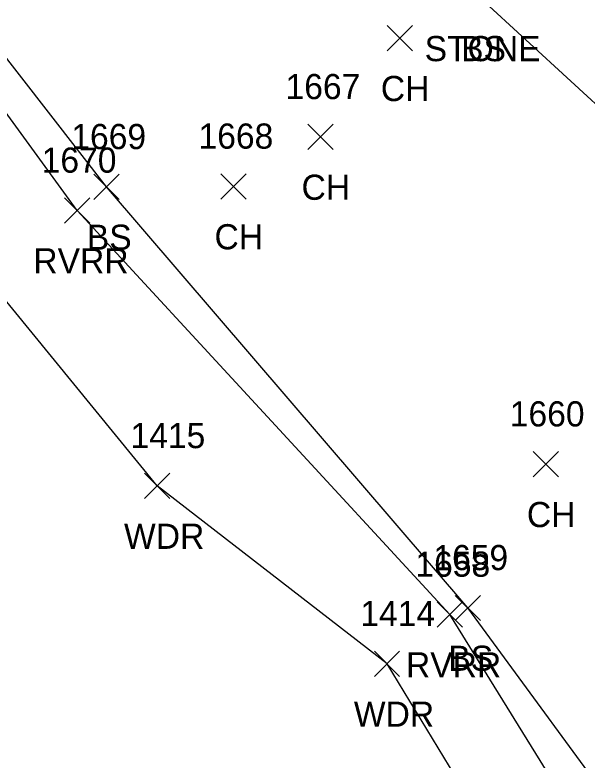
# Model space of a CAD drawing. Extents: x 1653908 to 1654393, y 539913 to 544256.
# Drawn here: x 1653996.7 to 1654042.2, y 541631.4 to 541690.6 of the extents above; entities that cross this region are included whole.
import ezdxf

# ---------------------------------------------------------------- set-up
doc = ezdxf.new("R2010")
doc.units = 0
for name, color, linetype in [('L_A', 7, 'Continuous'), ('L_I', 7, 'Continuous'), ('L_TIC', 7, 'Continuous'), ('LASF', 7, 'Continuous'), ('LAWA', 7, 'Continuous'), ('LAWE', 7, 'Continuous'), ('LELB', 7, 'Continuous')]:
    doc.layers.add(name, color=color, linetype=linetype)

msp = doc.modelspace()

# ---------------------------------------------------------------- linework, layer by layer
at = {"layer": 'L_TIC'}
for points in [[(1654026.298, 541687.741), (1654028.298, 541689.741)], [(1654028.298, 541687.741), (1654026.298, 541689.741)], [(1654019.996, 541679.896), (1654021.996, 541681.896)], [(1654021.996, 541679.896), (1654019.996, 541681.896)], [(1654002.972, 541675.925), (1654004.972, 541677.925)], [(1654004.972, 541675.925), (1654002.972, 541677.925)], [(1654013.076, 541675.961), (1654015.076, 541677.961)], [(1654015.076, 541675.961), (1654013.076, 541677.961)], [(1654000.648, 541674.052), (1654002.648, 541676.052)], [(1654002.648, 541674.052), (1654000.648, 541676.052)], [(1654037.909, 541653.887), (1654039.909, 541655.887)], [(1654039.909, 541653.887), (1654037.909, 541655.887)], [(1654007.006, 541652.162), (1654009.006, 541654.162)], [(1654009.006, 541652.162), (1654007.006, 541654.162)], [(1654031.71, 541642.467), (1654033.71, 541644.467)], [(1654033.71, 541642.467), (1654031.71, 541644.467)], [(1654030.273, 541641.945), (1654032.273, 541643.945)], [(1654032.273, 541641.945), (1654030.273, 541643.945)], [(1654025.279, 541638.027), (1654027.279, 541640.027)], [(1654027.279, 541638.027), (1654025.279, 541640.027)]]:
    msp.add_lwpolyline(points, dxfattribs=at)
at = {"layer": 'LASF'}
msp.add_lwpolyline([(1654082.441, 541647.339), (1654081.332, 541637.747), (1654062.765, 541655.231), (1654048.059, 541678.769), (1654033.728, 541691.913)], dxfattribs=at)
at = {"layer": 'LAWA'}
msp.add_lwpolyline([(1654038.913, 541618.252), (1654026.279, 541639.027), (1654008.006, 541653.162), (1653988.111, 541677.483), (1653964.639, 541704.447), (1653928.638, 541724.558)], dxfattribs=at)
at = {"layer": 'LAWE'}
msp.add_lwpolyline([(1654165.746, 541453.299), (1654145.371, 541485.64), (1654128.334, 541517.883), (1654118.977, 541538.058), (1654102.878, 541558.426), (1654087.635, 541571.291), (1654080.686, 541574.229), (1654068.7, 541590.649), (1654047.982, 541616.505), (1654043.581, 541623.07), (1654031.273, 541642.945), (1654001.648, 541675.052), (1653981.817, 541702.274), (1653972.906, 541712.113), (1653946.212, 541722.655), (1653929.327, 541730.47)], dxfattribs=at)
at = {"layer": 'LELB'}
msp.add_lwpolyline([(1654046.042, 541625.31), (1654032.71, 541643.467), (1654003.972, 541676.925), (1653983.751, 541702.944), (1653973.709, 541712.938), (1653947.901, 541724.236), (1653930.458, 541733.898)], dxfattribs=at)

# ---------------------------------------------------------------- texts
at = {"layer": 'L_A'}
for s, p in [('STONE', (1654029.271, 541686.913)), ('STONE', (1654029.271, 541686.913)), ('BS', (1654032.169, 541686.913)), ('CH', (1654025.786, 541683.741)), ('CH', (1654019.484, 541675.896)), ('BS', (1654002.413, 541671.925)), ('CH', (1654012.564, 541671.961)), ('RVRR', (1653998.159, 541670.052)), ('CH', (1654037.397, 541649.887)), ('WDR', (1654005.368, 541648.162)), ('BS', (1654031.151, 541638.467)), ('RVRR', (1654027.785, 541637.945)), ('WDR', (1654023.641, 541634.027))]:
    msp.add_text(s, height=2, dxfattribs=at).set_placement(p)
at = {"layer": 'L_I'}
for s, p in [('1667', (1654018.209, 541683.896)), ('1669', (1654001.177, 541679.925)), ('1668', (1654011.289, 541679.961)), ('1670', (1653998.821, 541678.052)), ('1660', (1654036.035, 541657.887)), ('1415', (1654005.881, 541656.162)), ('1659', (1654029.962, 541646.467)), ('1658', (1654028.533, 541645.945)), ('1414', (1654024.153, 541642.027))]:
    msp.add_text(s, height=2, dxfattribs=at).set_placement(p)

doc.saveas('drawing.dxf')
